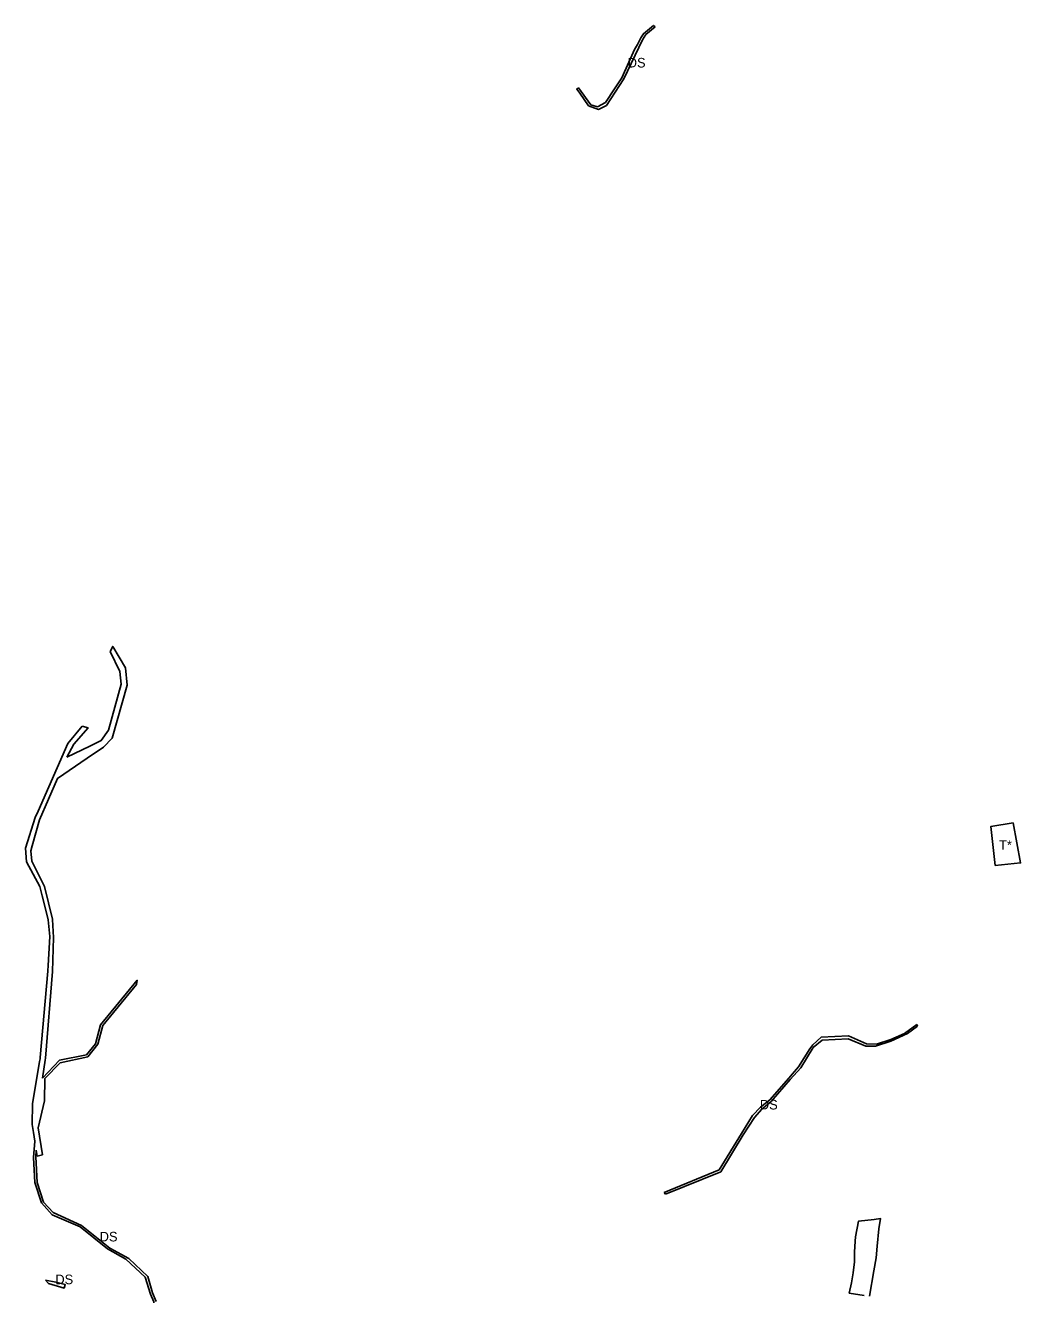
# Model space of a CAD drawing. Extents: x -477304 to -465641, y -1159113 to -1149285.
# Drawn here: x -473406 to -472472, y -1151597 to -1150406 of the extents above; entities that cross this region are included whole.
import ezdxf

# ---------------------------------------------------------------- set-up
doc = ezdxf.new("R2010")
doc.units = 0
doc.layers.add('17', color=7, linetype='Continuous')
doc.layers.add('35', color=7, linetype='Continuous')

msp = doc.modelspace()

# ---------------------------------------------------------------- linework, layer by layer
at = {"layer": '17'}
msp.add_lwpolyline([(-472495.9, -1151194.6), (-472472.1, -1151192.1), (-472479.1, -1151154.5), (-472500, -1151157.8), (-472495.9, -1151194.6)], dxfattribs=at)
at = {"layer": '35'}
for p, q in [((-472823.9, -1150415), (-472815, -1150407.8)), ((-472815, -1150407.8), (-472816.6, -1150406.4)), ((-472844.4, -1150456.6), (-472827, -1150419.8)), ((-472828.5, -1150418.1), (-472831.6, -1150424.3)), ((-472827, -1150419.8), (-472823.9, -1150415)), ((-472834.5, -1150429.1), (-472846.4, -1150455.5)), ((-472831.6, -1150424.3), (-472834.5, -1150429.1)), ((-472846.4, -1150455.5), (-472853.1, -1150465.9)), ((-472853.1, -1150465.9), (-472861.5, -1150478.6)), ((-472869.2, -1150482.9), (-472875.3, -1150481)), ((-472861.5, -1150478.6), (-472869.2, -1150482.9)), ((-473316.2, -1151024.3), (-473327.9, -1151067.5)), ((-473367, -1151093), (-473360.4, -1151080.6)), ((-473399.6, -1151176.1), (-473392.7, -1151151.8)), ((-473400.9, -1151180.7), (-473399.6, -1151176.1)), ((-473399.8, -1151190.3), (-473400.9, -1151180.7)), ((-473389.5, -1151211.1), (-473399.8, -1151190.3)), ((-473387.9, -1151214.3), (-473389.5, -1151211.1)), ((-473380.6, -1151244.8), (-473387.9, -1151214.3)), ((-473380.5, -1151245.3), (-473380.6, -1151244.8)), ((-473384.6, -1151288.4), (-473384.9, -1151293.3)), ((-473333.4, -1151344.5), (-473301.6, -1151306.2)), ((-473338, -1151362), (-473333.4, -1151344.5)), ((-472593.7, -1151359.4), (-472578.3, -1151352.2)), ((-472578.3, -1151352.2), (-472568.9, -1151345.1)), ((-472568.9, -1151345.1), (-472569.6, -1151343.7)), ((-473347.2, -1151373.9), (-473338, -1151362)), ((-472607.4, -1151362.1), (-472616.6, -1151361.8)), ((-473392.1, -1151374.5), (-473392.2, -1151376)), ((-473348.6, -1151372.1), (-473373.9, -1151377.1)), ((-473373.2, -1151379.6), (-473347.2, -1151373.9)), ((-473373.9, -1151377.1), (-473389.9, -1151393.9)), ((-473387.7, -1151394.4), (-473373.2, -1151379.6)), ((-472688.4, -1151395.4), (-472678.4, -1151384.2)), ((-473388, -1151415.2), (-473387.7, -1151394.4)), ((-473393.8, -1151440.5), (-473388, -1151415.2)), ((-472716.2, -1151421.2), (-472723.6, -1151429.2)), ((-472707.3, -1151414.3), (-472716.2, -1151421.2)), ((-472723.6, -1151429.2), (-472734.1, -1151446)), ((-473399.7, -1151437.6), (-473398.4, -1151445)), ((-473398.4, -1151445), (-473397.1, -1151453)), ((-473389.8, -1151466.1), (-473393.8, -1151440.5)), ((-472734.1, -1151446), (-472755, -1151480.1)), ((-473396.2, -1151467.8), (-473395.7, -1151461.5)), ((-473394.9, -1151491.8), (-473396.2, -1151467.8)), ((-472755, -1151480.1), (-472806.5, -1151501.4)), ((-472805.3, -1151503), (-472753.3, -1151481.9)), ((-473397, -1151491.9), (-473390.7, -1151511.1)), ((-472806.5, -1151501.4), (-472805.3, -1151503)), ((-473390.7, -1151511.1), (-473380.8, -1151522.2)), ((-472606.7, -1151551.6), (-472605.2, -1151535.4)), ((-473308.9, -1151563.1), (-473326.7, -1151553.5)), ((-472627.4, -1151547), (-472627.9, -1151557.2)), ((-472627.1, -1151542.8), (-472627.4, -1151547)), ((-472607.7, -1151562.5), (-472606.7, -1151551.6)), ((-473291, -1151580.1), (-473308.9, -1151563.1)), ((-472609.8, -1151574.8), (-472607.7, -1151562.5)), ((-472629.2, -1151576.7), (-472630.8, -1151586)), ((-472613.9, -1151598.4), (-472609.8, -1151574.8)), ((-473377.5, -1151585.3), (-473387, -1151583.5)), ((-473286.7, -1151595.4), (-473291, -1151580.1)), ((-472630.8, -1151586), (-472633.1, -1151595.6)), ((-473283.1, -1151603.6), (-473286.7, -1151595.4)), ((-472633.1, -1151595.6), (-472618.9, -1151597.9))]:
    msp.add_line(p, q, dxfattribs=at)
for points in [[(-472816.6, -1150406.4), (-472826, -1150414.3), (-472828.5, -1150418.1)], [(-472877.5, -1150481.9), (-472868.3, -1150485.3), (-472860.8, -1150481.4), (-472844.4, -1150456.6)], [(-472875.3, -1150481), (-472887, -1150465), (-472888.6, -1150466.1), (-472885.8, -1150470.1), (-472877.5, -1150481.9)], [(-473324.4, -1151075.1), (-473310.5, -1151025.5), (-473312, -1151009), (-473324, -1150989), (-473326.3, -1150993.9)], [(-473326.3, -1150993.9), (-473317.2, -1151012.5), (-473316.2, -1151024.3)], [(-473352.6, -1151063.7), (-473366, -1151080.2), (-473394, -1151143.6)], [(-473360.4, -1151080.6), (-473347.1, -1151065.5), (-473352.6, -1151063.7)], [(-473327.9, -1151067.5), (-473334.8, -1151077.2), (-473345.5, -1151082.5), (-473367, -1151093)], [(-473348, -1151093.9), (-473332.5, -1151083.4), (-473324.4, -1151075.1)], [(-473392.7, -1151151.8), (-473375.7, -1151112.8), (-473348, -1151093.9)], [(-473394, -1151143.6), (-473396.6, -1151149.6), (-473405.9, -1151178.4)], [(-473405.9, -1151178.4), (-473404.9, -1151191), (-473392.3, -1151214.3)], [(-473392.3, -1151214.3), (-473390.1, -1151223), (-473384.6, -1151245.2), (-473384.5, -1151245.6)], [(-473384.5, -1151245.6), (-473383.1, -1151261.1), (-473384.6, -1151288.4)], [(-473380.6, -1151293.9), (-473379.4, -1151262.1), (-473380.5, -1151245.3)], [(-473384.9, -1151293.3), (-473384.9, -1151293.8), (-473392.1, -1151374.5)], [(-473389.9, -1151393.9), (-473387.3, -1151377.2), (-473387.1, -1151375.2), (-473380.6, -1151293.9)], [(-473301.6, -1151306.2), (-473300.9, -1151302.2), (-473335.6, -1151344), (-473340.2, -1151361.8), (-473348.6, -1151372.1)], [(-472569.6, -1151343.7), (-472581, -1151352.1), (-472593.7, -1151357.7), (-472607.4, -1151362.1)], [(-472667.2, -1151362.9), (-472669.9, -1151366.5), (-472680.4, -1151383.3), (-472686.2, -1151389.9)], [(-472678.4, -1151384.2), (-472666.7, -1151365.3), (-472658.3, -1151358.3)], [(-472616.6, -1151361.8), (-472633.7, -1151354.2), (-472659.3, -1151355.6), (-472667.2, -1151362.9)], [(-472658.3, -1151358.3), (-472633.8, -1151357), (-472617.2, -1151364.1), (-472608.2, -1151363.9), (-472593.7, -1151359.4)], [(-473392.2, -1151376), (-473392.7, -1151378.5), (-473399.2, -1151418.2), (-473399.7, -1151437.6)], [(-472714.9, -1151423), (-472706, -1151415.8), (-472688.4, -1151395.4)], [(-472686.2, -1151389.9), (-472689.7, -1151394), (-472707.3, -1151414.3)], [(-472753.3, -1151481.9), (-472732.5, -1151447.1), (-472721.8, -1151431), (-472714.9, -1151423)], [(-473397.1, -1151453), (-473398.2, -1151468.6), (-473397, -1151491.9)], [(-473395.7, -1151461.5), (-473394.8, -1151467.2), (-473389.8, -1151466.1)], [(-473379.8, -1151520.1), (-473388.9, -1151510.4), (-473394.9, -1151491.8)], [(-473380.8, -1151522.2), (-473354.6, -1151533.6), (-473329, -1151554.2), (-473311.8, -1151563.8), (-473293.6, -1151580.7), (-473288.6, -1151596.7), (-473285.5, -1151603.9), (-473286.9, -1151626.6)], [(-473326.7, -1151553.5), (-473353.3, -1151532.4), (-473379.8, -1151520.1)], [(-472609.6, -1151526.5), (-472624.3, -1151528.3), (-472627.1, -1151542.8)], [(-472605.2, -1151535.4), (-472603.4, -1151525.8), (-472609.6, -1151526.5)], [(-472627.9, -1151557.2), (-472628, -1151566.2), (-472629.2, -1151576.7)], [(-473387, -1151583.5), (-473384.2, -1151586.6), (-473369.6, -1151591), (-473368.6, -1151587.7), (-473377.5, -1151585.3)]]:
    msp.add_lwpolyline(points, dxfattribs=at)

# ---------------------------------------------------------------- texts
at = {"layer": '17'}
msp.add_text('T*', height=9, dxfattribs=at).set_placement((-472492.3, -1151179.8))
at = {"layer": '35'}
for p in [(-472840.7, -1150445.9), (-472716.7, -1151423.4), (-473336.2, -1151547.2), (-473377.8, -1151587.3)]:
    msp.add_text('DS', height=9, dxfattribs=at).set_placement(p)

doc.saveas('drawing.dxf')
